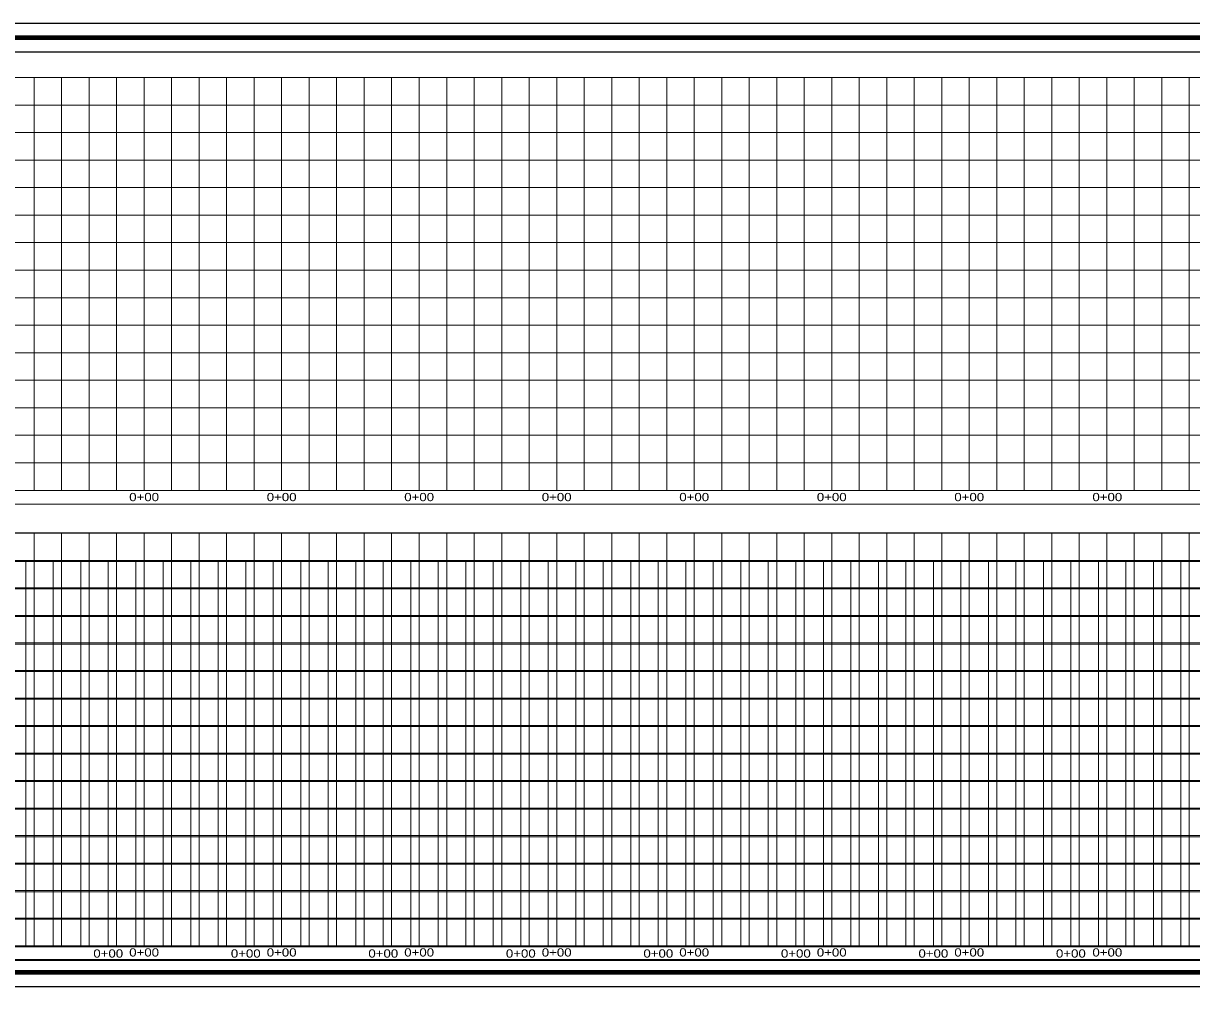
# Model space of a CAD drawing. Extents: x 2246932 to 2264252, y 7095151 to 7098651.
# Drawn here: x 2255652 to 2259900, y 7095151 to 7098651 of the extents above; entities that cross this region are included whole.
import ezdxf
from ezdxf.enums import TextEntityAlignment as Align

# ---------------------------------------------------------------- set-up
doc = ezdxf.new("R2010")
doc.units = 0
doc.header["$LTSCALE"] = 12
for name, color, linetype, lineweight in [('1', 7, 'Continuous', 80), ('59', 7, 'Continuous', 13), ('60', 7, 'Continuous', 13), ('62', 7, 'Continuous', 13), ('63', 7, 'Continuous', 25)]:
    doc.layers.add(name, color=color, linetype=linetype, lineweight=lineweight)
doc.layers.add('22', color=7, linetype='Continuous')
doc.layers.add('23', color=7, linetype='Continuous')

msp = doc.modelspace()

# ---------------------------------------------------------------- linework, layer by layer
at = {"layer": '1'}
for p, q in [((2264052.09, 7098598.35), (2247157.09, 7098598.35)), ((2247157.09, 7095203.35), (2264052.09, 7095203.35))]:
    msp.add_line(p, q, dxfattribs=at)
at = {"layer": '1', "lineweight": 25}
msp.add_line((2247104.59, 7095150.85), (2264104.59, 7095150.85), dxfattribs=at)
msp.add_lwpolyline([(2264104.59, 7095150.85), (2264104.59, 7098650.85), (2247104.59, 7098650.85), (2247104.59, 7095150.85)], dxfattribs=at)
at = {"layer": '59'}
for p, q in [((2247310.97, 7096695.64), (2262610.97, 7096695.64)), ((2255660.97, 7096695.64), (2255660.97, 7095995.64)), ((2255760.97, 7096695.64), (2255760.97, 7095995.64)), ((2255860.97, 7096695.64), (2255860.97, 7095995.64)), ((2255960.97, 7096695.64), (2255960.97, 7095995.64)), ((2256060.97, 7096695.64), (2256060.97, 7095995.64)), ((2256160.97, 7096695.64), (2256160.97, 7095995.64)), ((2256260.97, 7096695.64), (2256260.97, 7095995.64)), ((2256360.97, 7096695.64), (2256360.97, 7095995.64)), ((2256460.97, 7096695.64), (2256460.97, 7095995.64)), ((2256560.97, 7096695.64), (2256560.97, 7095995.64)), ((2256660.97, 7096695.64), (2256660.97, 7095995.64)), ((2256760.97, 7096695.64), (2256760.97, 7095995.64)), ((2256860.97, 7096695.64), (2256860.97, 7095995.64)), ((2256960.97, 7096695.64), (2256960.97, 7095995.64)), ((2257060.97, 7096695.64), (2257060.97, 7095995.64)), ((2257160.97, 7096695.64), (2257160.97, 7095995.64)), ((2257260.97, 7096695.64), (2257260.97, 7095995.64)), ((2257360.97, 7096695.64), (2257360.97, 7095995.64)), ((2257460.97, 7096695.64), (2257460.97, 7095995.64)), ((2257560.97, 7096695.64), (2257560.97, 7095995.64)), ((2257660.97, 7096695.64), (2257660.97, 7095995.64)), ((2257760.97, 7096695.64), (2257760.97, 7095995.64)), ((2257860.97, 7096695.64), (2257860.97, 7095995.64)), ((2257960.97, 7096695.64), (2257960.97, 7095995.64)), ((2258060.97, 7096695.64), (2258060.97, 7095995.64)), ((2258160.97, 7096695.64), (2258160.97, 7095995.64)), ((2258260.97, 7096695.64), (2258260.97, 7095995.64)), ((2258360.97, 7096695.64), (2258360.97, 7095995.64)), ((2258460.97, 7096695.64), (2258460.97, 7095995.64)), ((2258560.97, 7096695.64), (2258560.97, 7095995.64)), ((2258660.97, 7096695.64), (2258660.97, 7095995.64)), ((2258760.97, 7096695.64), (2258760.97, 7095995.64)), ((2258860.97, 7096695.64), (2258860.97, 7095995.64)), ((2258960.97, 7096695.64), (2258960.97, 7095995.64)), ((2259060.97, 7096695.64), (2259060.97, 7095995.64)), ((2259160.97, 7096695.64), (2259160.97, 7095995.64)), ((2259260.97, 7096695.64), (2259260.97, 7095995.64)), ((2259360.97, 7096695.64), (2259360.97, 7095995.64)), ((2259460.97, 7096695.64), (2259460.97, 7095995.64)), ((2259560.97, 7096695.64), (2259560.97, 7095995.64)), ((2259660.97, 7096695.64), (2259660.97, 7095995.64)), ((2259760.97, 7096695.64), (2259760.97, 7095995.64)), ((2259860.97, 7096695.64), (2259860.97, 7095995.64)), ((2255660.97, 7095995.64), (2255660.97, 7095295.64)), ((2255760.97, 7095995.64), (2255760.97, 7095295.64)), ((2255860.97, 7095995.64), (2255860.97, 7095295.64)), ((2255960.97, 7095995.64), (2255960.97, 7095295.64)), ((2256060.97, 7095995.64), (2256060.97, 7095295.64)), ((2256160.97, 7095995.64), (2256160.97, 7095295.64)), ((2256260.97, 7095995.64), (2256260.97, 7095295.64)), ((2256360.97, 7095995.64), (2256360.97, 7095295.64)), ((2256460.97, 7095995.64), (2256460.97, 7095295.64)), ((2256560.97, 7095995.64), (2256560.97, 7095295.64)), ((2256660.97, 7095995.64), (2256660.97, 7095295.64)), ((2256760.97, 7095995.64), (2256760.97, 7095295.64)), ((2256860.97, 7095995.64), (2256860.97, 7095295.64)), ((2256960.97, 7095995.64), (2256960.97, 7095295.64)), ((2257060.97, 7095995.64), (2257060.97, 7095295.64)), ((2257160.97, 7095995.64), (2257160.97, 7095295.64)), ((2257260.97, 7095995.64), (2257260.97, 7095295.64)), ((2257360.97, 7095995.64), (2257360.97, 7095295.64)), ((2257460.97, 7095995.64), (2257460.97, 7095295.64)), ((2257560.97, 7095995.64), (2257560.97, 7095295.64)), ((2257660.97, 7095995.64), (2257660.97, 7095295.64)), ((2257760.97, 7095995.64), (2257760.97, 7095295.64)), ((2257860.97, 7095995.64), (2257860.97, 7095295.64)), ((2257960.97, 7095995.64), (2257960.97, 7095295.64)), ((2258060.97, 7095995.64), (2258060.97, 7095295.64)), ((2258160.97, 7095995.64), (2258160.97, 7095295.64)), ((2258260.97, 7095995.64), (2258260.97, 7095295.64)), ((2258360.97, 7095995.64), (2258360.97, 7095295.64)), ((2258460.97, 7095995.64), (2258460.97, 7095295.64)), ((2258560.97, 7095995.64), (2258560.97, 7095295.64)), ((2258660.97, 7095995.64), (2258660.97, 7095295.64)), ((2258760.97, 7095995.64), (2258760.97, 7095295.64)), ((2258860.97, 7095995.64), (2258860.97, 7095295.64)), ((2258960.97, 7095995.64), (2258960.97, 7095295.64)), ((2259060.97, 7095995.64), (2259060.97, 7095295.64)), ((2259160.97, 7095995.64), (2259160.97, 7095295.64)), ((2259260.97, 7095995.64), (2259260.97, 7095295.64)), ((2259360.97, 7095995.64), (2259360.97, 7095295.64)), ((2259460.97, 7095995.64), (2259460.97, 7095295.64)), ((2259560.97, 7095995.64), (2259560.97, 7095295.64)), ((2259660.97, 7095995.64), (2259660.97, 7095295.64)), ((2259760.97, 7095995.64), (2259760.97, 7095295.64)), ((2259860.97, 7095995.64), (2259860.97, 7095295.64)), ((2262610.97, 7095295.64), (2247310.97, 7095295.64)), ((2262610.97, 7095245.64), (2247310.97, 7095245.64))]:
    msp.add_line(p, q, dxfattribs=at)
for points in [[(2247460.97, 7096595.64), (2262460.97, 7096595.64), (2262610.97, 7096595.64)], [(2247460.97, 7096495.64), (2262460.97, 7096495.64), (2262610.97, 7096495.64)], [(2247460.97, 7096395.64), (2262460.97, 7096395.64), (2262610.97, 7096395.64)], [(2247460.97, 7096295.64), (2262460.97, 7096295.64), (2262610.97, 7096295.64)], [(2247460.97, 7096195.64), (2262460.97, 7096195.64), (2262610.97, 7096195.64)], [(2247454.92, 7096095.64), (2262460.97, 7096095.64), (2262610.97, 7096095.64)], [(2247460.97, 7095995.64), (2262460.97, 7095995.64), (2262610.97, 7095995.64)], [(2247460.97, 7095895.64), (2262460.97, 7095895.64), (2262610.97, 7095895.64)], [(2247460.97, 7095795.64), (2262460.97, 7095795.64), (2262610.97, 7095795.64)], [(2247460.97, 7095695.64), (2262460.97, 7095695.64), (2262610.97, 7095695.64)], [(2247460.97, 7095595.64), (2262460.97, 7095595.64), (2262610.97, 7095595.64)], [(2247460.97, 7095495.64), (2262460.97, 7095495.64), (2262610.97, 7095495.64)], [(2247460.97, 7095395.64), (2262460.97, 7095395.64), (2262610.97, 7095395.64)]]:
    msp.add_lwpolyline(points, dxfattribs=at)
at = {"layer": '60'}
for p, q in [((2252310.97, 7096695.64), (2262610.97, 7096695.64)), ((2255660.97, 7096695.64), (2255660.97, 7095995.64)), ((2255760.97, 7096695.64), (2255760.97, 7095995.64)), ((2255860.97, 7096695.64), (2255860.97, 7095995.64)), ((2255960.97, 7096695.64), (2255960.97, 7095995.64)), ((2256060.97, 7096695.64), (2256060.97, 7095995.64)), ((2256160.97, 7096695.64), (2256160.97, 7095995.64)), ((2256260.97, 7096695.64), (2256260.97, 7095995.64)), ((2256360.97, 7096695.64), (2256360.97, 7095995.64)), ((2256460.97, 7096695.64), (2256460.97, 7095995.64)), ((2256560.97, 7096695.64), (2256560.97, 7095995.64)), ((2256660.97, 7096695.64), (2256660.97, 7095995.64)), ((2256760.97, 7096695.64), (2256760.97, 7095995.64)), ((2256860.97, 7096695.64), (2256860.97, 7095995.64)), ((2256960.97, 7096695.64), (2256960.97, 7095995.64)), ((2257060.97, 7096695.64), (2257060.97, 7095995.64)), ((2257160.97, 7096695.64), (2257160.97, 7095995.64)), ((2257260.97, 7096695.64), (2257260.97, 7095995.64)), ((2257360.97, 7096695.64), (2257360.97, 7095995.64)), ((2257460.97, 7096695.64), (2257460.97, 7095995.64)), ((2257560.97, 7096695.64), (2257560.97, 7095995.64)), ((2257660.97, 7096695.64), (2257660.97, 7095995.64)), ((2257760.97, 7096695.64), (2257760.97, 7095995.64)), ((2257860.97, 7096695.64), (2257860.97, 7095995.64)), ((2257960.97, 7096695.64), (2257960.97, 7095995.64)), ((2258060.97, 7096695.64), (2258060.97, 7095995.64)), ((2258160.97, 7096695.64), (2258160.97, 7095995.64)), ((2258260.97, 7096695.64), (2258260.97, 7095995.64)), ((2258360.97, 7096695.64), (2258360.97, 7095995.64)), ((2258460.97, 7096695.64), (2258460.97, 7095995.64)), ((2258560.97, 7096695.64), (2258560.97, 7095995.64)), ((2258660.97, 7096695.64), (2258660.97, 7095995.64)), ((2258760.97, 7096695.64), (2258760.97, 7095995.64)), ((2258860.97, 7096695.64), (2258860.97, 7095995.64)), ((2258960.97, 7096695.64), (2258960.97, 7095995.64)), ((2259060.97, 7096695.64), (2259060.97, 7095995.64)), ((2259160.97, 7096695.64), (2259160.97, 7095995.64)), ((2259260.97, 7096695.64), (2259260.97, 7095995.64)), ((2259360.97, 7096695.64), (2259360.97, 7095995.64)), ((2259460.97, 7096695.64), (2259460.97, 7095995.64)), ((2259560.97, 7096695.64), (2259560.97, 7095995.64)), ((2259660.97, 7096695.64), (2259660.97, 7095995.64)), ((2259760.97, 7096695.64), (2259760.97, 7095995.64)), ((2259860.97, 7096695.64), (2259860.97, 7095995.64)), ((2255660.97, 7095995.64), (2255660.97, 7095295.64)), ((2255760.97, 7095995.64), (2255760.97, 7095295.64)), ((2255860.97, 7095995.64), (2255860.97, 7095295.64)), ((2255960.97, 7095995.64), (2255960.97, 7095295.64)), ((2256060.97, 7095995.64), (2256060.97, 7095295.64)), ((2256160.97, 7095995.64), (2256160.97, 7095295.64)), ((2256260.97, 7095995.64), (2256260.97, 7095295.64)), ((2256360.97, 7095995.64), (2256360.97, 7095295.64)), ((2256460.97, 7095995.64), (2256460.97, 7095295.64)), ((2256560.97, 7095995.64), (2256560.97, 7095295.64)), ((2256660.97, 7095995.64), (2256660.97, 7095295.64)), ((2256760.97, 7095995.64), (2256760.97, 7095295.64)), ((2256860.97, 7095995.64), (2256860.97, 7095295.64)), ((2256960.97, 7095995.64), (2256960.97, 7095295.64)), ((2257060.97, 7095995.64), (2257060.97, 7095295.64)), ((2257160.97, 7095995.64), (2257160.97, 7095295.64)), ((2257260.97, 7095995.64), (2257260.97, 7095295.64)), ((2257360.97, 7095995.64), (2257360.97, 7095295.64)), ((2257460.97, 7095995.64), (2257460.97, 7095295.64)), ((2257560.97, 7095995.64), (2257560.97, 7095295.64)), ((2257660.97, 7095995.64), (2257660.97, 7095295.64)), ((2257760.97, 7095995.64), (2257760.97, 7095295.64)), ((2257860.97, 7095995.64), (2257860.97, 7095295.64)), ((2257960.97, 7095995.64), (2257960.97, 7095295.64)), ((2258060.97, 7095995.64), (2258060.97, 7095295.64)), ((2258160.97, 7095995.64), (2258160.97, 7095295.64)), ((2258260.97, 7095995.64), (2258260.97, 7095295.64)), ((2258360.97, 7095995.64), (2258360.97, 7095295.64)), ((2258460.97, 7095995.64), (2258460.97, 7095295.64)), ((2258560.97, 7095995.64), (2258560.97, 7095295.64)), ((2258660.97, 7095995.64), (2258660.97, 7095295.64)), ((2258760.97, 7095995.64), (2258760.97, 7095295.64)), ((2258860.97, 7095995.64), (2258860.97, 7095295.64)), ((2258960.97, 7095995.64), (2258960.97, 7095295.64)), ((2259060.97, 7095995.64), (2259060.97, 7095295.64)), ((2259160.97, 7095995.64), (2259160.97, 7095295.64)), ((2259260.97, 7095995.64), (2259260.97, 7095295.64)), ((2259360.97, 7095995.64), (2259360.97, 7095295.64)), ((2259460.97, 7095995.64), (2259460.97, 7095295.64)), ((2259560.97, 7095995.64), (2259560.97, 7095295.64)), ((2259660.97, 7095995.64), (2259660.97, 7095295.64)), ((2259760.97, 7095995.64), (2259760.97, 7095295.64)), ((2259860.97, 7095995.64), (2259860.97, 7095295.64)), ((2262610.97, 7095295.64), (2252310.97, 7095295.64)), ((2262610.97, 7095245.64), (2252310.97, 7095245.64))]:
    msp.add_line(p, q, dxfattribs=at)
for points in [[(2252460.97, 7096595.64), (2262460.97, 7096595.64), (2262610.97, 7096595.64)], [(2252460.97, 7096495.64), (2262460.97, 7096495.64), (2262610.97, 7096495.64)], [(2252460.97, 7096395.64), (2262460.97, 7096395.64), (2262610.97, 7096395.64)], [(2252460.97, 7096295.64), (2262460.97, 7096295.64), (2262610.97, 7096295.64)], [(2252460.97, 7096195.64), (2262460.97, 7096195.64), (2262610.97, 7096195.64)], [(2252454.92, 7096095.64), (2262460.97, 7096095.64), (2262610.97, 7096095.64)], [(2252460.97, 7095995.64), (2262460.97, 7095995.64), (2262610.97, 7095995.64)], [(2252460.97, 7095895.64), (2262460.97, 7095895.64), (2262610.97, 7095895.64)], [(2252460.97, 7095795.64), (2262460.97, 7095795.64), (2262610.97, 7095795.64)], [(2252460.97, 7095695.64), (2262460.97, 7095695.64), (2262610.97, 7095695.64)], [(2252460.97, 7095595.64), (2262460.97, 7095595.64), (2262610.97, 7095595.64)], [(2252460.97, 7095495.64), (2262460.97, 7095495.64), (2262610.97, 7095495.64)], [(2252460.97, 7095395.64), (2262460.97, 7095395.64), (2262610.97, 7095395.64)]]:
    msp.add_lwpolyline(points, dxfattribs=at)
at = {"layer": '62'}
for p, q in [((2247941.45, 7098454.14), (2263241.45, 7098454.14)), ((2255691.45, 7098454.14), (2255691.45, 7096954.14)), ((2255791.45, 7098454.14), (2255791.45, 7096954.14)), ((2255891.45, 7098454.14), (2255891.45, 7096954.14)), ((2255991.45, 7098454.14), (2255991.45, 7096954.14)), ((2256091.45, 7098454.14), (2256091.45, 7096954.14)), ((2256191.45, 7098454.14), (2256191.45, 7096954.14)), ((2256291.45, 7098454.14), (2256291.45, 7096954.14)), ((2256391.45, 7098454.14), (2256391.45, 7096954.14)), ((2256491.45, 7098454.14), (2256491.45, 7096954.14)), ((2256591.45, 7098454.14), (2256591.45, 7096954.14)), ((2256691.45, 7098454.14), (2256691.45, 7096954.14)), ((2256791.45, 7098454.14), (2256791.45, 7096954.14)), ((2256891.45, 7098454.14), (2256891.45, 7096954.14)), ((2256991.45, 7098454.14), (2256991.45, 7096954.14)), ((2257091.45, 7098454.14), (2257091.45, 7096954.14)), ((2257191.45, 7098454.14), (2257191.45, 7096954.14)), ((2257291.45, 7098454.14), (2257291.45, 7096954.14)), ((2257391.45, 7098454.14), (2257391.45, 7096954.14)), ((2257491.45, 7098454.14), (2257491.45, 7096954.14)), ((2257591.45, 7098454.14), (2257591.45, 7096954.14)), ((2257691.45, 7098454.14), (2257691.45, 7096954.14)), ((2257791.45, 7098454.14), (2257791.45, 7096954.14)), ((2257891.45, 7098454.14), (2257891.45, 7096954.14)), ((2257991.45, 7098454.14), (2257991.45, 7096954.14)), ((2258091.45, 7098454.14), (2258091.45, 7096954.14)), ((2258191.45, 7098454.14), (2258191.45, 7096954.14)), ((2258291.45, 7098454.14), (2258291.45, 7096954.14)), ((2258391.45, 7098454.14), (2258391.45, 7096954.14)), ((2258491.45, 7098454.14), (2258491.45, 7096954.14)), ((2258591.45, 7098454.14), (2258591.45, 7096954.14)), ((2258691.45, 7098454.14), (2258691.45, 7096954.14)), ((2258791.45, 7098454.14), (2258791.45, 7096954.14)), ((2258891.45, 7098454.14), (2258891.45, 7096954.14)), ((2258991.45, 7098454.14), (2258991.45, 7096954.14)), ((2259091.45, 7098454.14), (2259091.45, 7096954.14)), ((2259191.45, 7098454.14), (2259191.45, 7096954.14)), ((2259291.45, 7098454.14), (2259291.45, 7096954.14)), ((2259391.45, 7098454.14), (2259391.45, 7096954.14)), ((2259491.45, 7098454.14), (2259491.45, 7096954.14)), ((2259591.45, 7098454.14), (2259591.45, 7096954.14)), ((2259691.45, 7098454.14), (2259691.45, 7096954.14)), ((2259791.45, 7098454.14), (2259791.45, 7096954.14)), ((2259891.45, 7098454.14), (2259891.45, 7096954.14)), ((2259241.45, 7097654.14), (2249441.45, 7097654.14)), ((2263241.45, 7096954.14), (2247941.45, 7096954.14)), ((2263241.45, 7096904.14), (2247941.45, 7096904.14)), ((2247941.45, 7096799.51), (2263241.45, 7096799.51)), ((2255691.45, 7096799.51), (2255691.45, 7095299.51)), ((2255791.45, 7096799.51), (2255791.45, 7095299.51)), ((2255891.45, 7096799.51), (2255891.45, 7095299.51)), ((2255991.45, 7096799.51), (2255991.45, 7095299.51)), ((2256091.45, 7096799.51), (2256091.45, 7095299.51)), ((2256191.45, 7096799.51), (2256191.45, 7095299.51)), ((2256291.45, 7096799.51), (2256291.45, 7095299.51)), ((2256391.45, 7096799.51), (2256391.45, 7095299.51)), ((2256491.45, 7096799.51), (2256491.45, 7095299.51)), ((2256591.45, 7096799.51), (2256591.45, 7095299.51)), ((2256691.45, 7096799.51), (2256691.45, 7095299.51)), ((2256791.45, 7096799.51), (2256791.45, 7095299.51)), ((2256891.45, 7096799.51), (2256891.45, 7095299.51)), ((2256991.45, 7096799.51), (2256991.45, 7095299.51)), ((2257091.45, 7096799.51), (2257091.45, 7095299.51)), ((2257191.45, 7096799.51), (2257191.45, 7095299.51)), ((2257291.45, 7096799.51), (2257291.45, 7095299.51)), ((2257391.45, 7096799.51), (2257391.45, 7095299.51)), ((2257491.45, 7096799.51), (2257491.45, 7095299.51)), ((2257591.45, 7096799.51), (2257591.45, 7095299.51)), ((2257691.45, 7096799.51), (2257691.45, 7095299.51)), ((2257791.45, 7096799.51), (2257791.45, 7095299.51)), ((2257891.45, 7096799.51), (2257891.45, 7095299.51)), ((2257991.45, 7096799.51), (2257991.45, 7095299.51)), ((2258091.45, 7096799.51), (2258091.45, 7095299.51)), ((2258191.45, 7096799.51), (2258191.45, 7095299.51)), ((2258291.45, 7096799.51), (2258291.45, 7095299.51)), ((2258391.45, 7096799.51), (2258391.45, 7095299.51)), ((2258491.45, 7096799.51), (2258491.45, 7095299.51)), ((2258591.45, 7096799.51), (2258591.45, 7095299.51)), ((2258691.45, 7096799.51), (2258691.45, 7095299.51)), ((2258791.45, 7096799.51), (2258791.45, 7095299.51)), ((2258891.45, 7096799.51), (2258891.45, 7095299.51)), ((2258991.45, 7096799.51), (2258991.45, 7095299.51)), ((2259091.45, 7096799.51), (2259091.45, 7095299.51)), ((2259191.45, 7096799.51), (2259191.45, 7095299.51)), ((2259291.45, 7096799.51), (2259291.45, 7095299.51)), ((2259391.45, 7096799.51), (2259391.45, 7095299.51)), ((2259491.45, 7096799.51), (2259491.45, 7095299.51)), ((2259591.45, 7096799.51), (2259591.45, 7095299.51)), ((2259691.45, 7096799.51), (2259691.45, 7095299.51)), ((2259791.45, 7096799.51), (2259791.45, 7095299.51)), ((2259891.45, 7096799.51), (2259891.45, 7095299.51)), ((2259241.45, 7095999.51), (2249441.45, 7095999.51)), ((2263241.45, 7095299.51), (2247941.45, 7095299.51)), ((2263241.45, 7095249.51), (2247941.45, 7095249.51))]:
    msp.add_line(p, q, dxfattribs=at)
for points in [[(2248091.45, 7098354.14), (2263091.45, 7098354.14), (2263241.45, 7098354.14)], [(2248091.45, 7098254.14), (2263091.45, 7098254.14), (2263241.45, 7098254.14)], [(2248091.45, 7098154.14), (2263091.45, 7098154.14), (2263241.45, 7098154.14)], [(2248091.45, 7098054.14), (2263091.45, 7098054.14), (2263241.45, 7098054.14)], [(2248091.45, 7097954.14), (2263091.45, 7097954.14), (2263241.45, 7097954.14)], [(2248091.45, 7097854.14), (2263091.45, 7097854.14), (2263241.45, 7097854.14)], [(2248091.45, 7097754.14), (2263091.45, 7097754.14), (2263241.45, 7097754.14)], [(2248091.45, 7097654.14), (2263091.45, 7097654.14), (2263241.45, 7097654.14)], [(2248091.45, 7097554.14), (2263091.45, 7097554.14), (2263241.45, 7097554.14)], [(2248091.45, 7097454.14), (2263091.45, 7097454.14), (2263241.45, 7097454.14)], [(2248091.45, 7097354.14), (2263091.45, 7097354.14), (2263241.45, 7097354.14)], [(2248091.45, 7097254.14), (2263091.45, 7097254.14), (2263241.45, 7097254.14)], [(2248091.45, 7097154.14), (2263091.45, 7097154.14), (2263241.45, 7097154.14)], [(2248091.45, 7097054.14), (2263091.45, 7097054.14), (2263241.45, 7097054.14)], [(2248091.45, 7096699.51), (2263091.45, 7096699.51), (2263241.45, 7096699.51)], [(2248091.45, 7096599.51), (2263091.45, 7096599.51), (2263241.45, 7096599.51)], [(2248091.45, 7096499.51), (2263091.45, 7096499.51), (2263241.45, 7096499.51)], [(2248091.45, 7096399.51), (2263091.45, 7096399.51), (2263241.45, 7096399.51)], [(2248091.45, 7096299.51), (2263091.45, 7096299.51), (2263241.45, 7096299.51)], [(2248091.45, 7096199.51), (2263091.45, 7096199.51), (2263241.45, 7096199.51)], [(2248091.45, 7096099.51), (2263091.45, 7096099.51), (2263241.45, 7096099.51)], [(2248091.45, 7095999.51), (2263091.45, 7095999.51), (2263241.45, 7095999.51)], [(2248091.45, 7095899.51), (2263091.45, 7095899.51), (2263241.45, 7095899.51)], [(2248091.45, 7095799.51), (2263091.45, 7095799.51), (2263241.45, 7095799.51)], [(2248091.45, 7095699.51), (2263091.45, 7095699.51), (2263241.45, 7095699.51)], [(2248091.45, 7095599.51), (2263091.45, 7095599.51), (2263241.45, 7095599.51)], [(2248091.45, 7095499.51), (2263091.45, 7095499.51), (2263241.45, 7095499.51)], [(2248091.45, 7095399.51), (2263091.45, 7095399.51), (2263241.45, 7095399.51)]]:
    msp.add_lwpolyline(points, dxfattribs=at)
at = {"layer": '63'}
msp.add_lwpolyline([(2252360.97, 7098548.06), (2262360.97, 7098548.06), (2262360.97, 7096798.06), (2252360.97, 7096798.06)], close=True, dxfattribs=at)

# ---------------------------------------------------------------- texts
at = {"layer": '22', "width": 1.2}
for p in [(2256091.45, 7096914.74), (2256591.45, 7096914.74), (2257091.45, 7096914.74), (2257591.45, 7096914.74), (2258091.45, 7096914.74), (2258591.45, 7096914.74), (2259091.45, 7096914.74), (2259593.49, 7096914.74), (2256091.45, 7095260.11), (2256591.45, 7095260.11), (2257091.45, 7095260.11), (2257591.45, 7095260.11), (2258091.45, 7095260.11), (2258591.45, 7095260.11), (2259091.45, 7095260.11), (2259593.49, 7095260.11)]:
    msp.add_text('0+00', height=30, dxfattribs=at).set_placement(p, align=Align.CENTER)
at = {"layer": '23', "width": 1.2}
for p in [(2255960.97, 7095256.23), (2256460.97, 7095256.23), (2256960.97, 7095256.23), (2257460.97, 7095256.23), (2257960.97, 7095256.23), (2258460.97, 7095256.23), (2258960.97, 7095256.23), (2259460.97, 7095256.23)]:
    msp.add_text('0+00', height=30, dxfattribs=at).set_placement(p, align=Align.CENTER)

doc.saveas('drawing.dxf')
